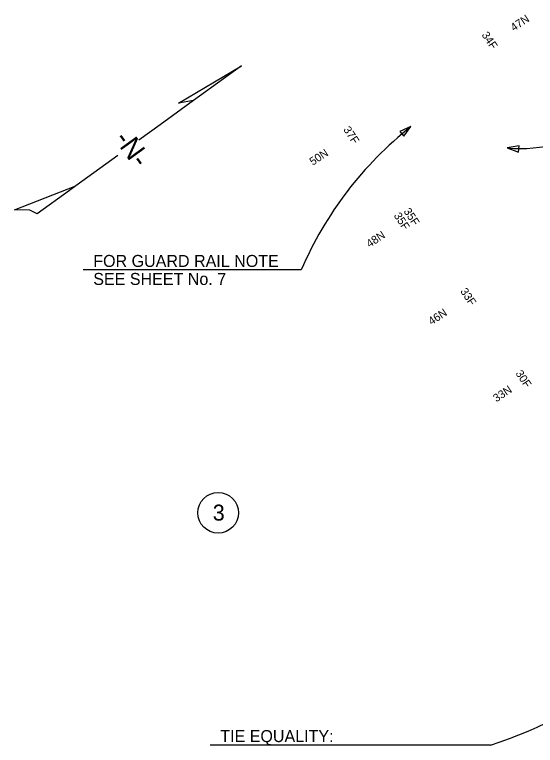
# Model space of a CAD drawing. Extents: x 1964849 to 1967422, y 1116563 to 1122210.
# Drawn here: x 1966684.2 to 1966944.5, y 1121844.7 to 1122209.9 of the extents above; entities that cross this region are included whole.
import ezdxf

# ---------------------------------------------------------------- set-up
doc = ezdxf.new("R2010")
doc.units = 0
for name, color, linetype in [('RD_EX_DV_TX_Prop', 7, 'Continuous'), ('RD_EX_Misc', 7, 'Continuous'), ('RD_HC_Data', 7, 'Continuous'), ('RD_PD_TX_CstnLmt', 7, 'Continuous'), ('RD_TX_Drainage', 7, 'Continuous'), ('RD_TX_Misc1', 7, 'Continuous')]:
    doc.layers.add(name, color=color, linetype=linetype)

msp = doc.modelspace()

# ---------------------------------------------------------------- linework, layer by layer
at = {"layer": 'RD_EX_DV_TX_Prop'}
msp.add_circle((1966785.94, 1121960.93), 10.18, dxfattribs=at)
at = {"layer": 'RD_EX_Misc'}
for p, q in [((1966766.12, 1122165.66), (1966797.54, 1122184.31)), ((1966797.54, 1122184.31), (1966773.54, 1122166.92)), ((1966773.54, 1122166.92), (1966756.91, 1122154.87)), ((1966773.54, 1122166.92), (1966766.12, 1122165.66)), ((1966756.91, 1122154.87), (1966746.3, 1122147.18)), ((1966735.71, 1122139.51), (1966714.73, 1122124.32)), ((1966684.19, 1122112.37), (1966714.73, 1122124.32)), ((1966714.73, 1122124.32), (1966711.56, 1122122.01)), ((1966711.56, 1122122.01), (1966695.48, 1122110.37))]:
    msp.add_line(p, q, dxfattribs=at)
msp.add_lwpolyline([(1966695.48, 1122110.37), (1966691.84, 1122112.1), (1966684.19, 1122112.37)], dxfattribs=at)
at = {"layer": 'RD_HC_Data'}
msp.add_line((1966922.03, 1121844.81), (1966781.97, 1121844.81), dxfattribs=at)
msp.add_arc((1966854.98, 1122052.8), 218.53, 287.8676, 329.6328, dxfattribs=at)
at = {"layer": 'RD_TX_Misc1'}
msp.add_line((1966827.42, 1122082.3), (1966718.49, 1122082.3), dxfattribs=at)
for points in [[(1966878.67, 1122149.12), (1966882.25, 1122153.94), (1966876.74, 1122151.56)], [(1966936.31, 1122144.34), (1966930.41, 1122143.27), (1966936.06, 1122141.25)]]:
    msp.add_lwpolyline(points, close=True, dxfattribs=at)
for centre, radius, start, end in [((1966936.78, 1122220.78), 77.77, 265.305, 339.6154), ((1966996.8, 1122009.48), 184.37, 128.4114, 156.734)]:
    msp.add_arc(centre, radius, start, end, dxfattribs=at)

# ---------------------------------------------------------------- texts
at = {"layer": 'RD_EX_DV_TX_Prop'}
msp.add_text('3', height=8, dxfattribs=at).set_placement((1966783.23, 1121957.01))
at = {"layer": 'RD_EX_Misc'}
msp.add_text('-N-', height=10, rotation=305.9228, dxfattribs=at).set_placement((1966733.68, 1122147.66))
at = {"layer": 'RD_HC_Data'}
msp.add_text('TIE EQUALITY:', height=6, dxfattribs=at).set_placement((1966786.97, 1121846.31))
at = {"layer": 'RD_PD_TX_CstnLmt'}
for s, p in [('34F', (1966917.41, 1122199.8)), ('37F', (1966848.28, 1122152.47)), ('35F', (1966878.39, 1122111.62)), ('35F', (1966873.5, 1122109.42)), ('33F', (1966906.74, 1122071.65)), ('30F', (1966934.34, 1122030.61))]:
    msp.add_text(s, height=4, rotation=303.6494, dxfattribs=at).set_placement(p)
at = {"layer": 'RD_TX_Drainage'}
for s, p in [('47N', (1966933.69, 1122201.4)), ('50N', (1966833.22, 1122134.35)), ('48N', (1966861.63, 1122093.32)), ('46N', (1966892.57, 1122054.54)), ('33N', (1966924.97, 1122016.06))]:
    msp.add_text(s, height=4, rotation=33.6494, dxfattribs=at).set_placement(p)
at = {"layer": 'RD_TX_Misc1'}
for s, p in [('FOR GUARD RAIL NOTE', (1966723.49, 1122083.8)), ('SEE SHEET No. 7', (1966723.49, 1122074.8))]:
    msp.add_text(s, height=6, dxfattribs=at).set_placement(p)

doc.saveas('drawing.dxf')
